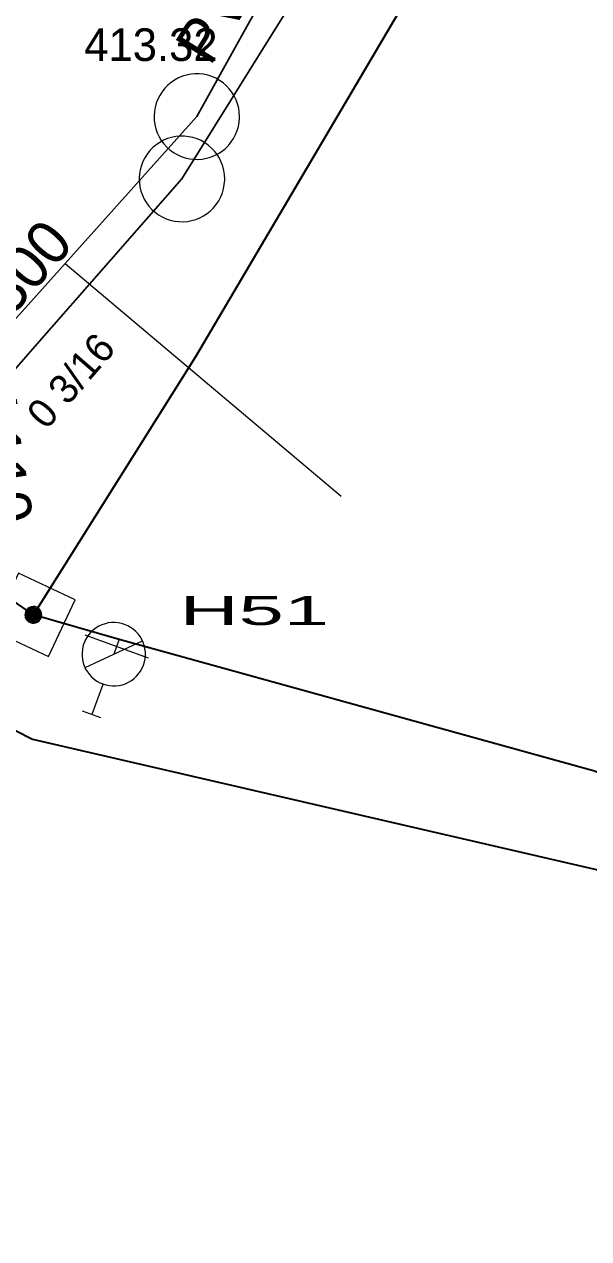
# Model space of a CAD drawing. Extents: x -772952 to -772403, y -1033777 to -1033210.
# Drawn here: x -772870.65 to -772855.07, y -1033589.93 to -1033556.43 of the extents above; entities that cross this region are included whole.
import ezdxf

# ---------------------------------------------------------------- set-up
doc = ezdxf.new("R2010")
doc.units = 0
doc.header["$LTSCALE"] = 0.36
for name, color, linetype, lineweight in [('15', 7, 'Continuous', 13), ('16', 7, 'Continuous', 35), ('2', 7, 'Continuous', 25), ('20', 7, 'Continuous', 13), ('21', 7, 'Continuous', 13), ('4', 7, 'Continuous', 13), ('57', 7, 'Continuous', 13), ('59', 7, 'Continuous', 13)]:
    doc.layers.add(name, color=color, linetype=linetype, lineweight=lineweight)
for name, color, linetype in [('17', 7, 'Continuous'), ('3', 7, 'Continuous'), ('6', 7, 'Continuous')]:
    doc.layers.add(name, color=color, linetype=linetype)

msp = doc.modelspace()

# ---------------------------------------------------------------- linework, layer by layer
at = {"layer": '15'}
msp.add_line((-772868.978, -1033573.271), (-772867.23, -1033573.912), dxfattribs=at)
for points in [[(-772870.172, -1033572.723), (-772870.178, -1033572.671), (-772870.195, -1033572.621), (-772870.224, -1033572.577), (-772870.261, -1033572.54), (-772870.306, -1033572.513), (-772870.356, -1033572.496), (-772870.409, -1033572.492), (-772870.461, -1033572.499), (-772870.51, -1033572.518), (-772870.553, -1033572.547), (-772870.589, -1033572.586), (-772870.615, -1033572.631), (-772870.631, -1033572.682), (-772870.634, -1033572.734), (-772870.626, -1033572.786), (-772870.606, -1033572.835), (-772870.575, -1033572.878), (-772870.536, -1033572.912), (-772870.49, -1033572.938), (-772870.439, -1033572.952), (-772870.386, -1033572.954), (-772870.335, -1033572.944), (-772870.287, -1033572.923), (-772870.244, -1033572.892), (-772870.21, -1033572.851), (-772870.186, -1033572.805), (-772870.174, -1033572.754)], [(-772870.202, -1033572.723), (-772870.208, -1033572.674), (-772870.225, -1033572.628), (-772870.253, -1033572.588), (-772870.29, -1033572.556), (-772870.334, -1033572.534), (-772870.382, -1033572.523), (-772870.431, -1033572.523), (-772870.478, -1033572.536), (-772870.521, -1033572.56), (-772870.557, -1033572.593), (-772870.584, -1033572.634), (-772870.6, -1033572.681), (-772870.604, -1033572.73), (-772870.597, -1033572.778), (-772870.578, -1033572.823), (-772870.548, -1033572.863), (-772870.51, -1033572.894), (-772870.466, -1033572.914), (-772870.418, -1033572.924), (-772870.369, -1033572.922), (-772870.322, -1033572.907), (-772870.279, -1033572.882), (-772870.245, -1033572.848), (-772870.219, -1033572.806), (-772870.205, -1033572.759)], [(-772870.232, -1033572.723), (-772870.238, -1033572.678), (-772870.255, -1033572.636), (-772870.283, -1033572.601), (-772870.319, -1033572.574), (-772870.361, -1033572.557), (-772870.406, -1033572.552), (-772870.451, -1033572.558), (-772870.492, -1033572.577), (-772870.527, -1033572.605), (-772870.554, -1033572.642), (-772870.57, -1033572.684), (-772870.574, -1033572.729), (-772870.567, -1033572.774), (-772870.548, -1033572.815), (-772870.519, -1033572.849), (-772870.482, -1033572.875), (-772870.439, -1033572.891), (-772870.394, -1033572.894), (-772870.349, -1033572.886), (-772870.309, -1033572.866), (-772870.275, -1033572.837), (-772870.249, -1033572.799), (-772870.235, -1033572.756)], [(-772870.262, -1033572.723), (-772870.267, -1033572.682), (-772870.285, -1033572.645), (-772870.312, -1033572.614), (-772870.347, -1033572.593), (-772870.387, -1033572.582), (-772870.428, -1033572.584), (-772870.467, -1033572.597), (-772870.501, -1033572.621), (-772870.526, -1033572.653), (-772870.541, -1033572.691), (-772870.544, -1033572.732), (-772870.536, -1033572.772), (-772870.516, -1033572.808), (-772870.487, -1033572.837), (-772870.45, -1033572.856), (-772870.41, -1033572.864), (-772870.369, -1033572.86), (-772870.331, -1033572.845), (-772870.299, -1033572.819), (-772870.276, -1033572.785), (-772870.263, -1033572.746)], [(-772870.292, -1033572.723), (-772870.297, -1033572.687), (-772870.315, -1033572.655), (-772870.341, -1033572.63), (-772870.375, -1033572.615), (-772870.411, -1033572.612), (-772870.446, -1033572.62), (-772870.477, -1033572.64), (-772870.5, -1033572.668), (-772870.513, -1033572.702), (-772870.513, -1033572.739), (-772870.502, -1033572.774), (-772870.481, -1033572.803), (-772870.451, -1033572.824), (-772870.416, -1033572.834), (-772870.379, -1033572.832), (-772870.345, -1033572.818), (-772870.318, -1033572.795), (-772870.299, -1033572.763), (-772870.292, -1033572.728)], [(-772870.322, -1033572.723), (-772870.327, -1033572.692), (-772870.344, -1033572.666), (-772870.37, -1033572.649), (-772870.4, -1033572.642), (-772870.431, -1033572.646), (-772870.458, -1033572.663), (-772870.476, -1033572.687), (-772870.484, -1033572.718), (-772870.48, -1033572.748), (-772870.465, -1033572.776), (-772870.441, -1033572.795), (-772870.411, -1033572.804), (-772870.38, -1033572.801), (-772870.352, -1033572.787), (-772870.332, -1033572.763), (-772870.322, -1033572.734)], [(-772870.352, -1033572.723), (-772870.357, -1033572.699), (-772870.374, -1033572.681), (-772870.397, -1033572.672), (-772870.421, -1033572.675), (-772870.442, -1033572.689), (-772870.453, -1033572.711), (-772870.453, -1033572.736), (-772870.441, -1033572.757), (-772870.421, -1033572.771), (-772870.396, -1033572.774), (-772870.373, -1033572.765), (-772870.357, -1033572.747)], [(-772870.382, -1033572.723), (-772870.387, -1033572.708), (-772870.402, -1033572.702), (-772870.417, -1033572.706), (-772870.424, -1033572.72), (-772870.42, -1033572.735), (-772870.407, -1033572.744), (-772870.392, -1033572.741), (-772870.382, -1033572.729)]]:
    msp.add_lwpolyline(points, close=True, dxfattribs=at)
at = {"layer": '16'}
for points in [[(-772870.403, -1033572.723), (-772865.918, -1033565.594), (-772858.208, -1033552.52), (-772854.394, -1033546.056), (-772851.153, -1033540.157), (-772849.795, -1033537.486), (-772845.024, -1033528.103), (-772839.019, -1033515.318), (-772837.765, -1033512.662), (-772833.548, -1033502.146)], [(-772870.403, -1033572.723), (-772872.293, -1033571.429), (-772871.831, -1033567.296), (-772871.53, -1033565.039)], [(-772759.272, -1033597.956), (-772777.938, -1033599.996), (-772804.013, -1033600.436), (-772815.616, -1033598.743), (-772829.081, -1033590.92), (-772839.554, -1033583.848), (-772854.907, -1033577.034), (-772868.037, -1033573.403), (-772870.403, -1033572.723)], [(-772871.839, -1033575.434), (-772870.427, -1033576.155), (-772849.008, -1033581.096), (-772841.55, -1033584.107), (-772822.87, -1033596.07), (-772815.517, -1033599.879), (-772800.324, -1033602.374), (-772785.625, -1033603.857), (-772759.69, -1033599.467), (-772726.1, -1033595.877), (-772705.133, -1033594.197), (-772687.467, -1033594.611), (-772649.087, -1033602.85)]]:
    msp.add_lwpolyline(points, dxfattribs=at)
at = {"layer": '2'}
for points in [[(-772856.3, -1033541.79), (-772858.202, -1033545.2), (-772859.574, -1033547.659), (-772861.584, -1033551.262), (-772862.915, -1033553.648), (-772863.687, -1033555.031), (-772864.505, -1033556.497), (-772865.89, -1033558.98)], [(-772856.75, -1033545.37), (-772857.835, -1033547.112), (-772858.191, -1033547.661), (-772859.727, -1033550.149), (-772861.201, -1033552.516), (-772862.495, -1033554.592), (-772863.958, -1033556.941), (-772866.3, -1033560.7)], [(-772865.89, -1033558.98), (-772869.521, -1033563.033), (-772871.824, -1033565.591), (-772872.027, -1033565.83), (-772872.43, -1033566.313)], [(-772866.3, -1033560.7), (-772867.35, -1033561.895), (-772868.261, -1033562.931), (-772870.428, -1033565.396), (-772871.974, -1033567.156), (-772874.87, -1033570.45)]]:
    msp.add_lwpolyline(points, dxfattribs=at)
at = {"layer": '20'}
for p, q in [((-772868.973, -1033574.178), (-772867.385, -1033573.442)), ((-772868.484, -1033574.642), (-772868.789, -1033575.472)), ((-772868.535, -1033575.565), (-772869.043, -1033575.378))]:
    msp.add_line(p, q, dxfattribs=at)
msp.add_lwpolyline([(-772869.005, -1033573.508), (-772869.032, -1033573.594), (-772869.05, -1033573.683), (-772869.059, -1033573.776), (-772869.058, -1033573.866), (-772869.046, -1033573.957), (-772869.026, -1033574.048), (-772868.996, -1033574.133), (-772868.959, -1033574.217), (-772868.91, -1033574.295), (-772868.856, -1033574.368), (-772868.794, -1033574.435), (-772868.725, -1033574.497), (-772868.65, -1033574.55), (-772868.571, -1033574.594), (-772868.486, -1033574.629), (-772868.398, -1033574.657), (-772868.309, -1033574.675), (-772868.218, -1033574.683), (-772868.125, -1033574.681), (-772868.034, -1033574.67), (-772867.945, -1033574.649), (-772867.859, -1033574.621), (-772867.776, -1033574.581), (-772867.697, -1033574.535), (-772867.623, -1033574.479), (-772867.556, -1033574.417), (-772867.497, -1033574.349), (-772867.443, -1033574.273), (-772867.399, -1033574.193), (-772867.362, -1033574.109), (-772867.336, -1033574.022), (-772867.318, -1033573.933), (-772867.31, -1033573.84), (-772867.311, -1033573.75), (-772867.322, -1033573.659), (-772867.342, -1033573.569), (-772867.373, -1033573.483), (-772867.41, -1033573.399), (-772867.458, -1033573.321), (-772867.512, -1033573.248), (-772867.575, -1033573.181), (-772867.644, -1033573.119), (-772867.719, -1033573.068), (-772867.798, -1033573.022), (-772867.883, -1033572.987), (-772867.971, -1033572.959), (-772868.061, -1033572.943), (-772868.151, -1033572.933), (-772868.243, -1033572.935), (-772868.335, -1033572.946), (-772868.423, -1033572.967), (-772868.51, -1033572.995), (-772868.593, -1033573.035), (-772868.672, -1033573.081), (-772868.745, -1033573.137), (-772868.813, -1033573.199), (-772868.872, -1033573.267), (-772868.926, -1033573.343), (-772868.97, -1033573.423), (-772869.004, -1033573.506)], dxfattribs=at)
at = {"layer": '21'}
msp.add_lwpolyline([(-772870.817, -1033571.571), (-772871.554, -1033573.136), (-772869.989, -1033573.873), (-772869.252, -1033572.308)], close=True, dxfattribs=at)
at = {"layer": '4'}
for points in [[(-772864.71, -1033558.98), (-772864.716, -1033558.861), (-772864.734, -1033558.744), (-772864.763, -1033558.628), (-772864.804, -1033558.517), (-772864.856, -1033558.41), (-772864.919, -1033558.309), (-772864.992, -1033558.214), (-772865.073, -1033558.128), (-772865.163, -1033558.05), (-772865.261, -1033557.981), (-772865.364, -1033557.923), (-772865.473, -1033557.876), (-772865.587, -1033557.839), (-772865.703, -1033557.814), (-772865.821, -1033557.802), (-772865.94, -1033557.801), (-772866.059, -1033557.812), (-772866.175, -1033557.835), (-772866.289, -1033557.869), (-772866.399, -1033557.915), (-772866.504, -1033557.972), (-772866.602, -1033558.039), (-772866.693, -1033558.115), (-772866.776, -1033558.2), (-772866.85, -1033558.294), (-772866.914, -1033558.394), (-772866.968, -1033558.5), (-772867.011, -1033558.611), (-772867.043, -1033558.725), (-772867.062, -1033558.843), (-772867.07, -1033558.962), (-772867.066, -1033559.08), (-772867.05, -1033559.198), (-772867.022, -1033559.314), (-772866.983, -1033559.426), (-772866.932, -1033559.534), (-772866.871, -1033559.636), (-772866.8, -1033559.732), (-772866.72, -1033559.819), (-772866.631, -1033559.899), (-772866.535, -1033559.969), (-772866.432, -1033560.029), (-772866.324, -1033560.078), (-772866.211, -1033560.116), (-772866.095, -1033560.142), (-772865.977, -1033560.157), (-772865.858, -1033560.16), (-772865.74, -1033560.151), (-772865.622, -1033560.13), (-772865.508, -1033560.097), (-772865.398, -1033560.053), (-772865.292, -1033559.998), (-772865.193, -1033559.932), (-772865.1, -1033559.857), (-772865.016, -1033559.773), (-772864.941, -1033559.681), (-772864.875, -1033559.582), (-772864.819, -1033559.477), (-772864.775, -1033559.367), (-772864.741, -1033559.253), (-772864.72, -1033559.136), (-772864.71, -1033559.017)], [(-772865.12, -1033560.7), (-772865.126, -1033560.581), (-772865.144, -1033560.464), (-772865.173, -1033560.348), (-772865.214, -1033560.237), (-772865.266, -1033560.13), (-772865.329, -1033560.029), (-772865.402, -1033559.934), (-772865.483, -1033559.848), (-772865.573, -1033559.77), (-772865.671, -1033559.701), (-772865.774, -1033559.643), (-772865.883, -1033559.596), (-772865.997, -1033559.559), (-772866.113, -1033559.534), (-772866.231, -1033559.522), (-772866.35, -1033559.521), (-772866.469, -1033559.532), (-772866.585, -1033559.555), (-772866.699, -1033559.589), (-772866.809, -1033559.635), (-772866.914, -1033559.692), (-772867.012, -1033559.759), (-772867.103, -1033559.835), (-772867.186, -1033559.92), (-772867.26, -1033560.014), (-772867.324, -1033560.114), (-772867.378, -1033560.22), (-772867.421, -1033560.331), (-772867.453, -1033560.445), (-772867.472, -1033560.563), (-772867.48, -1033560.682), (-772867.476, -1033560.8), (-772867.46, -1033560.918), (-772867.432, -1033561.034), (-772867.393, -1033561.146), (-772867.342, -1033561.254), (-772867.281, -1033561.356), (-772867.21, -1033561.452), (-772867.13, -1033561.539), (-772867.041, -1033561.619), (-772866.945, -1033561.689), (-772866.842, -1033561.749), (-772866.734, -1033561.798), (-772866.621, -1033561.836), (-772866.505, -1033561.862), (-772866.387, -1033561.877), (-772866.268, -1033561.88), (-772866.15, -1033561.871), (-772866.032, -1033561.85), (-772865.918, -1033561.817), (-772865.808, -1033561.773), (-772865.702, -1033561.718), (-772865.603, -1033561.652), (-772865.51, -1033561.577), (-772865.426, -1033561.493), (-772865.351, -1033561.401), (-772865.285, -1033561.302), (-772865.229, -1033561.197), (-772865.185, -1033561.087), (-772865.151, -1033560.973), (-772865.13, -1033560.856), (-772865.12, -1033560.737)]]:
    msp.add_lwpolyline(points, close=True, dxfattribs=at)
at = {"layer": '57'}
msp.add_line((-772869.521, -1033563.033), (-772861.9, -1033569.45), dxfattribs=at)
at = {"layer": '59'}
msp.add_lwpolyline([(-772868.037, -1033573.403), (-772868.105, -1033573.592), (-772868.185, -1033573.809)], dxfattribs=at)

# ---------------------------------------------------------------- texts
at = {"layer": '17'}
msp.add_text('PE DN 100 d 110 ', height=1.2, rotation=279, dxfattribs=at).set_placement((-772873.535, -1033557.959))
at = {"layer": '20', "width": 2.1}
msp.add_text('H51 ', height=0.8, dxfattribs=at).set_placement((-772866.359, -1033573.004))
at = {"layer": '3'}
for s, height, rotation, p in [('PVC DN 300', 1.2, 58, (-772865.52, -1033557.613)), ('PVC DN 300', 1.2, 49, (-772875.275, -1033569.439)), ('0 3/16 ', 0.8, 49, (-772870.043, -1033567.646))]:
    msp.add_text(s, height=height, rotation=rotation, dxfattribs=at).set_placement(p)
at = {"layer": '6'}
msp.add_text('413.32', height=0.9, dxfattribs=at).set_placement((-772868.998, -1033557.446))

doc.saveas('drawing.dxf')
